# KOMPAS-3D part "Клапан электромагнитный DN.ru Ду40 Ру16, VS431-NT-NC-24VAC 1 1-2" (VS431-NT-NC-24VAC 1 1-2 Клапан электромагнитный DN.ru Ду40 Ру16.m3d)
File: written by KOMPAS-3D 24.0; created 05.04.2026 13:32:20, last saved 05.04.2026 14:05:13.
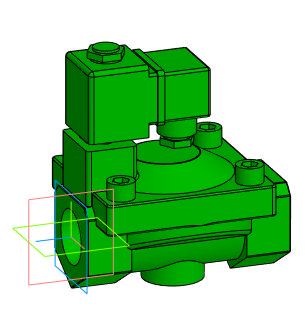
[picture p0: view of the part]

Document properties: Автор: artio; Полное имя файла: C:\Users\artio\OneDrive\Рабочий стол\Клапан электромагнитный DN.ru\VS431\VS431-NT-NC\VS431-NT-NC-24VAC\Ду40\VS431-NT-NC-24VAC 1 1-2 Клапан электромагнитный DN.ru Ду40 Ру16.m3d

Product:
- Body: Тело 1  | qty 1
    Масса: 3.859459
- Part/product: Клапан электромагнитный DN.ru Ду40 Ру16  | designation VS431-NT-NC-24VAC 1 1-2
    Масса: 2.285
    Раздел спецификации: Прочие изделия
    Примечание: D130-05511
    additional columns: ef56311e-7521-43dc-8291-0e6108b3d81d; artio; c; Шероховатость не задана; Да

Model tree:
1. Операция без истории:1

Expressions: VS431-NT-NC-24VAC 1 1-2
